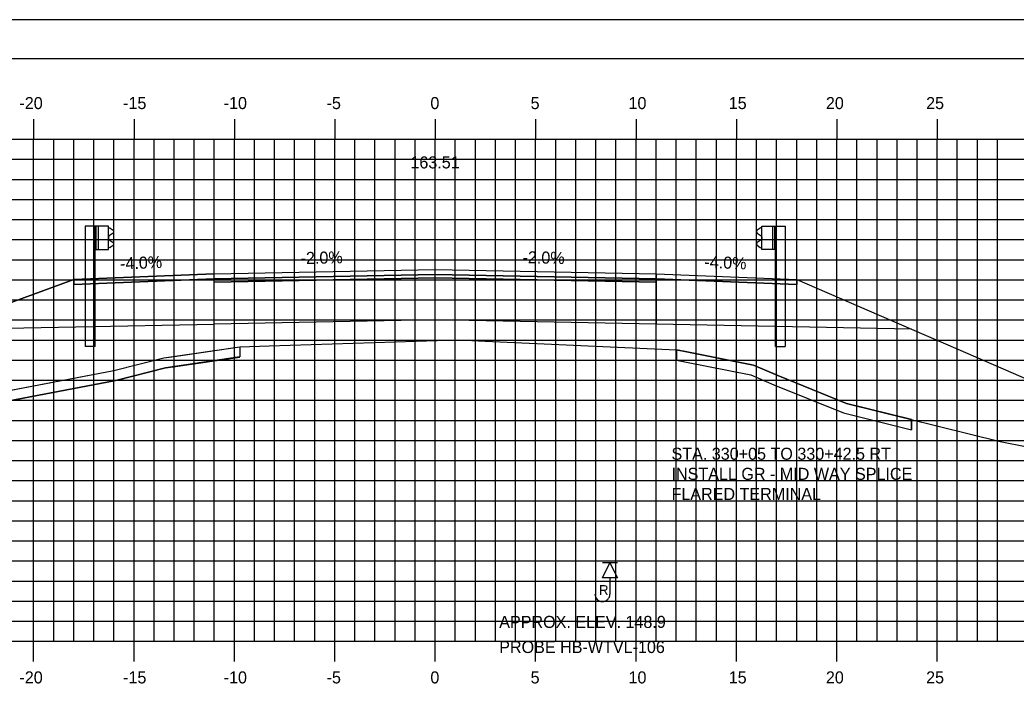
# Model space of a CAD drawing. Extents: x 1141202 to 1141372, y 608981 to 609091.
# Drawn here: x 1141264.83 to 1141314.44, y 609057.55 to 609091.28 of the extents above; entities that cross this region are included whole.
import ezdxf

# ---------------------------------------------------------------- set-up
doc = ezdxf.new("R2010")
doc.units = 0
for name, color, linetype in [('ANNOTATION', 7, 'Continuous'), ('BORDER', 7, 'Continuous'), ('D_Guardrail_Beam_Lt', 7, 'Continuous'), ('D_Guardrail_Beam_Rt', 7, 'Continuous'), ('D_Guardrail_ConcBarrier', 7, 'Continuous'), ('D_Roadway_Centerline', 7, 'Continuous'), ('D_Roadway_Centerline_Text', 7, 'Continuous'), ('D_Roadway_Edge_Shoulder', 7, 'Continuous'), ('D_Roadway_Edge_TW', 7, 'Continuous'), ('D_Roadway_Pavement', 7, 'Continuous'), ('D_Roadway_SlopeLines', 7, 'Continuous'), ('D_Roadway_SubGrade', 7, 'Continuous'), ('H_V ANNOTATION', 7, 'Continuous'), ('MAJOR', 7, 'Continuous'), ('MINOR', 7, 'Continuous'), ('PLOT BOUNDARY', 7, 'Continuous'), ('ROCKS', 7, 'Continuous'), ('S_Roadway_Centerline', 7, 'Continuous'), ('SHADING', 7, 'Continuous')]:
    doc.layers.add(name, color=color, linetype=linetype)

msp = doc.modelspace()

# ---------------------------------------------------------------- linework, layer by layer
msp.add_lwpolyline([(1141252.234, 609072.746), (1141257.978, 609074.853), (1141260.705, 609075.853), (1141267.513, 609078.349), (1141267.514, 609078.349), (1141274.514, 609078.629), (1141285.514, 609078.849), (1141296.514, 609078.629), (1141303.514, 609078.349), (1141309.224, 609075.875), (1141311.532, 609074.875), (1141326.721, 609068.292)])
at = {"layer": 'BORDER'}
msp.add_lwpolyline([(1141210.514, 608984.335), (1141370.514, 608984.335), (1141370.514, 609089.335), (1141210.514, 609089.335)], close=True, dxfattribs=at)
at = {"layer": 'D_Guardrail_Beam_Lt'}
for p, q in [((1141268.085, 609081.012), (1141268.085, 609075.012)), ((1141268.556, 609081.012), (1141268.085, 609081.012)), ((1141269.243, 609081.012), (1141268.556, 609081.012)), ((1141268.556, 609081.012), (1141268.556, 609079.846)), ((1141268.618, 609081.012), (1141268.618, 609079.846)), ((1141268.723, 609081.012), (1141268.723, 609079.846)), ((1141269.243, 609079.846), (1141269.243, 609081.012)), ((1141269.243, 609080.929), (1141269.318, 609080.915)), ((1141269.477, 609080.665), (1141269.282, 609080.529)), ((1141269.333, 609080.908), (1141269.477, 609080.808)), ((1141269.248, 609080.464), (1141269.248, 609080.394)), ((1141269.282, 609080.33), (1141269.477, 609080.193)), ((1141268.556, 609079.846), (1141269.243, 609079.846)), ((1141268.577, 609075.012), (1141268.577, 609079.846)), ((1141269.318, 609079.944), (1141269.243, 609079.929)), ((1141269.477, 609080.05), (1141269.333, 609079.95)), ((1141268.577, 609075.012), (1141268.085, 609075.012))]:
    msp.add_line(p, q, dxfattribs=at)
for centre, major_axis, start_param, end_param in [((1141269.31, 609080.874), (0.0417, 0), 0.959931, 1.376053), ((1141269.427, 609080.736), (0.0877, 0), 5.323254, 7.243116), ((1141269.327, 609080.464), (-0.0789, 0), 5.323254, 6.283185), ((1141269.327, 609080.394), (-0.0789, 0), 6.283185, 7.243116), ((1141269.427, 609080.122), (0.0877, 0), 5.323254, 7.243116), ((1141269.31, 609079.984), (0.0417, 0), 4.907132, 5.323254)]:
    msp.add_ellipse(centre, major_axis=major_axis, ratio=0.995501, start_param=start_param, end_param=end_param, dxfattribs=at)
at = {"layer": 'D_Guardrail_Beam_Rt'}
for p, q in [((1141301.695, 609080.908), (1141301.552, 609080.808)), ((1141301.552, 609080.665), (1141301.747, 609080.529)), ((1141301.785, 609080.929), (1141301.711, 609080.915)), ((1141301.747, 609080.33), (1141301.552, 609080.194)), ((1141301.781, 609080.465), (1141301.781, 609080.394)), ((1141301.552, 609080.051), (1141301.695, 609079.951)), ((1141301.711, 609079.944), (1141301.785, 609079.929))]:
    msp.add_line(p, q, dxfattribs=at)
for centre, major_axis, start_param, end_param in [((1141301.602, 609080.737), (-0.0877, 0), 5.323254, 7.243116), ((1141301.719, 609080.874), (-0.0417, 0), 4.907132, 5.323254), ((1141301.602, 609080.122), (-0.0877, 0), 5.323254, 7.243116), ((1141301.702, 609080.465), (0.0789, 0), 0, 0.959931), ((1141301.702, 609080.394), (0.0789, 0), 5.323254, 6.283185), ((1141301.719, 609079.985), (-0.0417, 0), 0.959931, 1.376053)]:
    msp.add_ellipse(centre, major_axis=major_axis, ratio=0.995501, start_param=start_param, end_param=end_param, dxfattribs=at)
at = {"layer": 'D_Guardrail_ConcBarrier'}
for p, q in [((1141301.785, 609081.013), (1141302.473, 609081.013)), ((1141301.785, 609079.846), (1141301.785, 609081.013)), ((1141302.306, 609081.013), (1141302.306, 609079.846)), ((1141302.41, 609081.013), (1141302.41, 609079.846)), ((1141302.473, 609081.013), (1141302.944, 609081.013)), ((1141302.473, 609081.013), (1141302.473, 609079.846)), ((1141302.944, 609081.013), (1141302.944, 609075.013)), ((1141302.473, 609079.846), (1141301.785, 609079.846)), ((1141302.452, 609075.013), (1141302.452, 609079.846)), ((1141302.452, 609075.013), (1141302.944, 609075.013))]:
    msp.add_line(p, q, dxfattribs=at)
at = {"layer": 'D_Roadway_Edge_Shoulder'}
for points in [[(1141274.514, 609078.629), (1141267.514, 609078.349), (1141267.514, 609078.099), (1141274.514, 609078.379)], [(1141296.514, 609078.629), (1141303.514, 609078.349), (1141303.514, 609078.099), (1141296.514, 609078.379)]]:
    msp.add_lwpolyline(points, close=True, dxfattribs=at)
at = {"layer": 'D_Roadway_Edge_TW'}
msp.add_lwpolyline([(1141274.514, 609078.379), (1141274.514, 609078.629), (1141285.514, 609078.849), (1141296.514, 609078.629), (1141296.514, 609078.379), (1141285.514, 609078.599)], close=True, dxfattribs=at)
at = {"layer": 'D_Roadway_Pavement'}
msp.add_lwpolyline([(1141274.514, 609078.212), (1141274.514, 609078.379), (1141285.514, 609078.599), (1141296.514, 609078.379), (1141296.514, 609078.212), (1141285.514, 609078.432)], close=True, dxfattribs=at)
at = {"layer": 'D_Roadway_SlopeLines'}
for p, q in [((1141275.785, 609074.994), (1141275.785, 609074.494)), ((1141297.528, 609074.852), (1141297.528, 609074.352)), ((1141309.224, 609071.383), (1141309.224, 609070.868))]:
    msp.add_line(p, q, dxfattribs=at)
for points in [[(1141309.224, 609075.875), (1141311.532, 609074.875)], [(1141311.532, 609074.875), (1141326.721, 609068.292)], [(1141260.705, 609071.631), (1141269.611, 609073.326), (1141272.09, 609073.949), (1141272.463, 609073.997), (1141275.785, 609074.489)], [(1141297.528, 609074.34), (1141297.94, 609074.253), (1141301.223, 609073.598), (1141302.379, 609073.104), (1141305.849, 609071.702), (1141309.224, 609070.868)]]:
    msp.add_lwpolyline(points, dxfattribs=at)
at = {"layer": 'D_Roadway_SubGrade'}
for points in [[(1141274.514, 609078.212), (1141274.514, 609078.379), (1141267.514, 609078.099), (1141267.514, 609078.349), (1141267.513, 609078.349), (1141260.705, 609075.853), (1141274.514, 609076.129)], [(1141274.514, 609076.129), (1141274.514, 609078.212), (1141285.514, 609078.432), (1141296.514, 609078.212), (1141296.514, 609076.129), (1141285.514, 609076.349)], [(1141296.514, 609078.212), (1141296.514, 609078.379), (1141303.514, 609078.099), (1141303.514, 609078.349), (1141303.514, 609078.349), (1141309.224, 609075.875), (1141296.514, 609076.129)]]:
    msp.add_lwpolyline(points, close=True, dxfattribs=at)
at = {"layer": 'MAJOR'}
for p, q in [((1141265.514, 609086.337), (1141265.514, 609085.335)), ((1141270.514, 609086.337), (1141270.514, 609085.335)), ((1141275.514, 609086.337), (1141275.514, 609085.335)), ((1141280.514, 609086.337), (1141280.514, 609085.335)), ((1141285.514, 609086.337), (1141285.514, 609085.335)), ((1141290.514, 609086.337), (1141290.514, 609085.335)), ((1141295.514, 609086.337), (1141295.514, 609085.335)), ((1141300.514, 609086.337), (1141300.514, 609085.335)), ((1141305.514, 609086.337), (1141305.514, 609085.335)), ((1141310.514, 609086.337), (1141310.514, 609085.335)), ((1141215.514, 609085.335), (1141355.514, 609085.335)), ((1141215.514, 609085.335), (1141355.514, 609085.335)), ((1141265.514, 609060.335), (1141265.514, 609085.335)), ((1141270.514, 609060.335), (1141270.514, 609085.335)), ((1141275.514, 609060.335), (1141275.514, 609085.335)), ((1141280.514, 609060.335), (1141280.514, 609085.335)), ((1141285.514, 609060.335), (1141285.514, 609085.335)), ((1141290.514, 609060.335), (1141290.514, 609085.335)), ((1141295.514, 609060.335), (1141295.514, 609085.335)), ((1141300.514, 609060.335), (1141300.514, 609085.335)), ((1141305.514, 609060.335), (1141305.514, 609085.335)), ((1141310.514, 609060.335), (1141310.514, 609085.335)), ((1141215.514, 609080.335), (1141355.514, 609080.335)), ((1141215.514, 609075.335), (1141355.514, 609075.335)), ((1141215.514, 609070.335), (1141355.514, 609070.335)), ((1141215.514, 609065.335), (1141355.514, 609065.335)), ((1141215.514, 609060.335), (1141355.514, 609060.335)), ((1141215.514, 609060.335), (1141355.514, 609060.335)), ((1141265.514, 609059.333), (1141265.514, 609060.335)), ((1141270.514, 609059.333), (1141270.514, 609060.335)), ((1141275.514, 609059.333), (1141275.514, 609060.335)), ((1141280.514, 609059.333), (1141280.514, 609060.335)), ((1141285.514, 609059.333), (1141285.514, 609060.335)), ((1141290.514, 609059.333), (1141290.514, 609060.335)), ((1141295.514, 609059.333), (1141295.514, 609060.335)), ((1141300.514, 609059.333), (1141300.514, 609060.335)), ((1141305.514, 609059.333), (1141305.514, 609060.335)), ((1141310.514, 609059.333), (1141310.514, 609060.335))]:
    msp.add_line(p, q, dxfattribs=at)
at = {"layer": 'MINOR'}
for p, q in [((1141266.514, 609060.335), (1141266.514, 609085.335)), ((1141267.514, 609060.335), (1141267.514, 609085.335)), ((1141268.514, 609060.335), (1141268.514, 609085.335)), ((1141269.514, 609060.335), (1141269.514, 609085.335)), ((1141271.514, 609060.335), (1141271.514, 609085.335)), ((1141272.514, 609060.335), (1141272.514, 609085.335)), ((1141273.514, 609060.335), (1141273.514, 609085.335)), ((1141274.514, 609060.335), (1141274.514, 609085.335)), ((1141276.514, 609060.335), (1141276.514, 609085.335)), ((1141277.514, 609060.335), (1141277.514, 609085.335)), ((1141278.514, 609060.335), (1141278.514, 609085.335)), ((1141279.514, 609060.335), (1141279.514, 609085.335)), ((1141281.514, 609060.335), (1141281.514, 609085.335)), ((1141282.514, 609060.335), (1141282.514, 609085.335)), ((1141283.514, 609060.335), (1141283.514, 609085.335)), ((1141284.514, 609060.335), (1141284.514, 609085.335)), ((1141286.514, 609060.335), (1141286.514, 609085.335)), ((1141287.514, 609060.335), (1141287.514, 609085.335)), ((1141288.514, 609060.335), (1141288.514, 609085.335)), ((1141289.514, 609060.335), (1141289.514, 609085.335)), ((1141291.514, 609060.335), (1141291.514, 609085.335)), ((1141292.514, 609060.335), (1141292.514, 609085.335)), ((1141293.514, 609060.335), (1141293.514, 609085.335)), ((1141294.514, 609060.335), (1141294.514, 609085.335)), ((1141296.514, 609060.335), (1141296.514, 609085.335)), ((1141297.514, 609060.335), (1141297.514, 609085.335)), ((1141298.514, 609060.335), (1141298.514, 609085.335)), ((1141299.514, 609060.335), (1141299.514, 609085.335)), ((1141301.514, 609060.335), (1141301.514, 609085.335)), ((1141302.514, 609060.335), (1141302.514, 609085.335)), ((1141303.514, 609060.335), (1141303.514, 609085.335)), ((1141304.514, 609060.335), (1141304.514, 609085.335)), ((1141306.514, 609060.335), (1141306.514, 609085.335)), ((1141307.514, 609060.335), (1141307.514, 609085.335)), ((1141308.514, 609060.335), (1141308.514, 609085.335)), ((1141309.514, 609060.335), (1141309.514, 609085.335)), ((1141311.514, 609060.335), (1141311.514, 609085.335)), ((1141312.514, 609060.335), (1141312.514, 609085.335)), ((1141313.514, 609060.335), (1141313.514, 609085.335)), ((1141215.514, 609084.335), (1141355.514, 609084.335)), ((1141215.514, 609083.335), (1141355.514, 609083.335)), ((1141215.514, 609082.335), (1141355.514, 609082.335)), ((1141215.514, 609081.335), (1141355.514, 609081.335)), ((1141215.514, 609079.335), (1141355.514, 609079.335)), ((1141215.514, 609078.335), (1141355.514, 609078.335)), ((1141215.514, 609077.335), (1141355.514, 609077.335)), ((1141215.514, 609076.335), (1141355.514, 609076.335)), ((1141215.514, 609074.335), (1141355.514, 609074.335)), ((1141215.514, 609073.335), (1141355.514, 609073.335)), ((1141215.514, 609072.335), (1141355.514, 609072.335)), ((1141215.514, 609071.335), (1141355.514, 609071.335)), ((1141215.514, 609069.335), (1141355.514, 609069.335)), ((1141215.514, 609068.335), (1141355.514, 609068.335)), ((1141215.514, 609067.335), (1141355.514, 609067.335)), ((1141215.514, 609066.335), (1141355.514, 609066.335)), ((1141215.514, 609064.335), (1141355.514, 609064.335)), ((1141215.514, 609063.335), (1141355.514, 609063.335)), ((1141215.514, 609062.335), (1141355.514, 609062.335)), ((1141215.514, 609061.335), (1141355.514, 609061.335))]:
    msp.add_line(p, q, dxfattribs=at)
at = {"layer": 'PLOT BOUNDARY'}
msp.add_lwpolyline([(1141202.421, 608981.276), (1141372.421, 608981.276), (1141372.421, 609091.276), (1141202.421, 609091.276)], close=True, dxfattribs=at)
at = {"layer": 'ROCKS'}
for p, q in [((1141294.583, 609064.235), (1141293.845, 609064.235)), ((1141294.214, 609063.497), (1141294.214, 609062.682))]:
    msp.add_line(p, q, dxfattribs=at)
msp.add_lwpolyline([(1141294.214, 609064.235), (1141294.583, 609063.497), (1141293.845, 609063.497)], close=True, dxfattribs=at)
msp.add_arc((1141293.841, 609062.682), 0.373, 180, 0, dxfattribs=at)
at = {"layer": 'S_Roadway_Centerline'}
msp.add_lwpolyline([(1141249.019, 609073.048), (1141259.669, 609072.048), (1141260.38, 609072.078), (1141269.503, 609073.815), (1141271.998, 609074.442), (1141272.395, 609074.492), (1141275.785, 609074.994), (1141277.244, 609075.043), (1141286.655, 609075.349), (1141288.005, 609075.271), (1141297.528, 609074.852), (1141298.041, 609074.742), (1141301.372, 609074.078), (1141302.571, 609073.566), (1141306.003, 609072.179), (1141313.651, 609070.289), (1141315, 609070.011)], dxfattribs=at)
at = {"layer": 'SHADING'}
for p, q in [((1141297.528, 609074.852), (1141297.528, 609074.352)), ((1141309.224, 609070.868), (1141309.224, 609071.383))]:
    msp.add_line(p, q, dxfattribs=at)
msp.add_lwpolyline([(1141275.785, 609074.994), (1141275.785, 609074.494), (1141272.09, 609073.949), (1141269.611, 609073.326), (1141260.705, 609071.631), (1141260.705, 609072.14), (1141269.503, 609073.815), (1141271.998, 609074.442)], close=True, dxfattribs=at)
for points in [[(1141309.224, 609071.383), (1141306.003, 609072.179), (1141302.571, 609073.566), (1141301.372, 609074.078), (1141298.041, 609074.742), (1141297.528, 609074.852)], [(1141297.528, 609074.352), (1141297.94, 609074.253), (1141301.223, 609073.598), (1141302.379, 609073.104), (1141305.849, 609071.702), (1141309.224, 609070.868)]]:
    msp.add_lwpolyline(points, dxfattribs=at)

# ---------------------------------------------------------------- texts
at = {"layer": 'ANNOTATION'}
for s, rotation, p in [('-2.0%', 1.1458, (1141278.817, 609079.115)), ('-2.0%', 358.8542, (1141289.857, 609079.162)), ('-4.0%', 2.2906, (1141269.83, 609078.842)), ('-4.0%', 357.7094, (1141298.91, 609078.934))]:
    msp.add_text(s, height=0.6, rotation=rotation, dxfattribs=at).set_placement(p)
for s, p in [('STA. 330+05 TO 330+42.5 RT', (1141297.281, 609069.373)), ('INSTALL GR - MID WAY SPLICE', (1141297.281, 609068.371)), ('FLARED TERMINAL', (1141297.281, 609067.369))]:
    msp.add_text(s, height=0.6, dxfattribs=at).set_placement(p)
at = {"layer": 'D_Roadway_Centerline'}
for s, p in [('C', (1141285.509, 609078.849)), ('C', (1141285.509, 609078.849)), ('L', (1141285.514, 609078.841)), ('L', (1141285.514, 609078.841))]:
    msp.add_text(s, height=0.0146, dxfattribs=at).set_placement(p)
at = {"layer": 'D_Roadway_Centerline_Text'}
msp.add_text('163.51', height=0.6, dxfattribs=at).set_placement((1141284.278, 609083.881))
at = {"layer": 'H_V ANNOTATION'}
for s, p in [('-20', (1141264.808, 609086.835)), ('-15', (1141269.971, 609086.835)), ('-10', (1141274.979, 609086.835)), ('-5', (1141280.105, 609086.835)), ('0', (1141285.273, 609086.835)), ('5', (1141290.265, 609086.835)), ('10', (1141295.14, 609086.835)), ('15', (1141300.131, 609086.835)), ('20', (1141304.968, 609086.835)), ('25', (1141309.96, 609086.835)), ('-20', (1141264.808, 609058.235)), ('-15', (1141269.971, 609058.235)), ('-10', (1141274.979, 609058.235)), ('-5', (1141280.105, 609058.235)), ('0', (1141285.273, 609058.235)), ('5', (1141290.265, 609058.235)), ('10', (1141295.14, 609058.235)), ('15', (1141300.131, 609058.235)), ('20', (1141304.968, 609058.235)), ('25', (1141309.96, 609058.235))]:
    msp.add_text(s, height=0.6, dxfattribs=at).set_placement(p)
at = {"layer": 'ROCKS'}
msp.add_text('R', height=0.492, dxfattribs=at).set_placement((1141293.669, 609062.639))
for s, p in [('APPROX. ELEV. 148.9', (1141288.701, 609060.998)), ('PROBE HB-WTVL-106', (1141288.701, 609059.748))]:
    msp.add_text(s, height=0.6, rotation=360, dxfattribs=at).set_placement(p)
at = {"layer": 'S_Roadway_Centerline'}
for s, p in [('C', (1141286.65, 609075.349)), ('L', (1141286.655, 609075.341))]:
    msp.add_text(s, height=0.0146, dxfattribs=at).set_placement(p)

doc.saveas('drawing.dxf')
